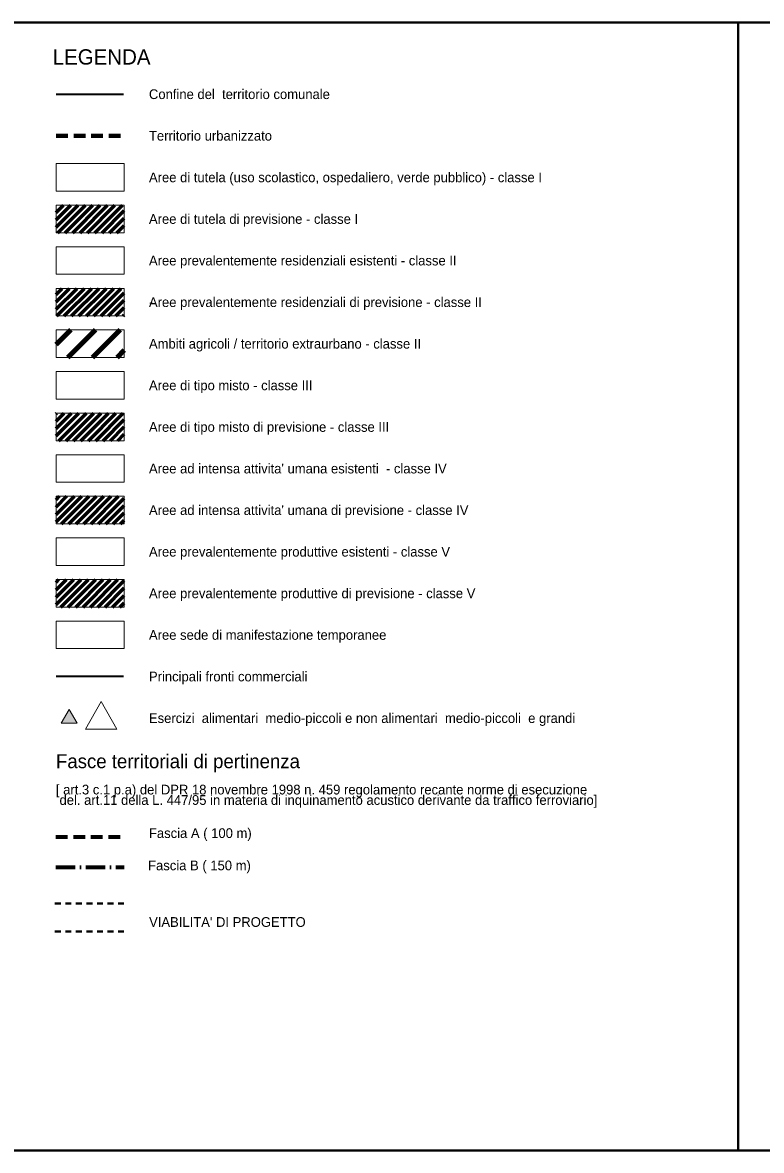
# Model space of a CAD drawing. Extents: x 650468 to 655025, y 889970 to 891591.
# Drawn here: x 651540 to 652602, y 889970 to 891591 of the extents above; entities that cross this region are included whole.
import ezdxf

# ---------------------------------------------------------------- set-up
doc = ezdxf.new("R2010")
doc.units = 0
doc.header["$LTSCALE"] = 5.6
for name, pattern in [('DOT_DASHED', [7.7, 5, -1.2, 0.3, -1.2]), ('MEDIUM_DASHED', [4.5, 3, -1.5]), ('SHORT_DASHED', [2.7, 1.5, -1.2])]:
    doc.linetypes.add(name, pattern=pattern)
doc.layers.add('61', color=7, linetype='Continuous', lineweight=35)

msp = doc.modelspace()

# ---------------------------------------------------------------- hatches: boundary and pattern name
at = {"layer": '61'}
msp.add_hatch(color=256, dxfattribs=at).paths.add_polyline_path([(651606.72, 890603.48), (651618.09, 890583.8), (651595.34, 890583.8)])

# ---------------------------------------------------------------- linework, layer by layer
for p, q in [((651587.95, 891488.17), (651684.93, 891488.17)), ((651684.52, 890650.98), (651587.94, 890650.98))]:
    msp.add_line(p, q, dxfattribs=at)
at = {"layer": '61', "linetype": 'MEDIUM_DASHED', "lineweight": 80}
msp.add_line((651587.94, 891428.36), (651685.6, 891428.36), dxfattribs=at)
at = {"layer": '61', "lineweight": 60}
for p, q in [((651587.94, 891318.24), (651598.26, 891328.56)), ((651587.94, 891307.64), (651608.86, 891328.56)), ((651587.94, 891297.03), (651619.47, 891328.56)), ((651590.48, 891288.96), (651630.08, 891328.56)), ((651601.08, 891288.96), (651640.68, 891328.56)), ((651611.69, 891288.96), (651651.29, 891328.56)), ((651622.3, 891288.96), (651661.9, 891328.56)), ((651632.9, 891288.96), (651672.5, 891328.56)), ((651643.51, 891288.96), (651683.11, 891328.56)), ((651654.12, 891288.96), (651685.86, 891320.7)), ((651664.72, 891288.96), (651685.86, 891310.1)), ((651675.33, 891288.96), (651685.86, 891299.49)), ((651587.94, 891200.22), (651596.7, 891208.98)), ((651587.94, 891189.61), (651607.31, 891208.98)), ((651587.94, 891179.01), (651617.92, 891208.98)), ((651588.92, 891169.38), (651628.52, 891208.98)), ((651599.53, 891169.38), (651639.13, 891208.98)), ((651610.14, 891169.38), (651649.74, 891208.98)), ((651620.74, 891169.38), (651660.34, 891208.98)), ((651631.35, 891169.38), (651670.95, 891208.98)), ((651641.95, 891169.38), (651681.55, 891208.98)), ((651652.56, 891169.38), (651685.86, 891202.68)), ((651663.17, 891169.38), (651685.86, 891192.07)), ((651673.77, 891169.38), (651685.86, 891181.47)), ((651684.38, 891169.38), (651685.86, 891170.86)), ((651587.94, 891028.58), (651588.94, 891029.58)), ((651587.94, 891017.97), (651599.55, 891029.58)), ((651587.94, 891007.36), (651610.16, 891029.58)), ((651587.94, 890996.76), (651620.76, 891029.58)), ((651591.77, 890989.98), (651631.37, 891029.58)), ((651602.38, 890989.98), (651641.98, 891029.58)), ((651612.98, 890989.98), (651652.58, 891029.58)), ((651623.59, 890989.98), (651663.19, 891029.58)), ((651634.2, 890989.98), (651673.8, 891029.58)), ((651644.8, 890989.98), (651684.4, 891029.58)), ((651655.41, 890989.98), (651685.86, 891020.43)), ((651666.02, 890989.98), (651685.86, 891009.82)), ((651676.62, 890989.98), (651685.86, 890999.22)), ((651587.94, 890905.03), (651592.89, 890909.98)), ((651587.94, 890894.43), (651603.49, 890909.98)), ((651587.94, 890883.82), (651614.1, 890909.98)), ((651587.94, 890873.21), (651624.71, 890909.98)), ((651595.71, 890870.38), (651635.31, 890909.98)), ((651606.32, 890870.38), (651645.92, 890909.98)), ((651616.93, 890870.38), (651656.53, 890909.98)), ((651627.53, 890870.38), (651667.13, 890909.98)), ((651638.14, 890870.38), (651677.74, 890909.98)), ((651648.75, 890870.38), (651685.86, 890907.49)), ((651659.35, 890870.38), (651685.86, 890896.89)), ((651669.96, 890870.38), (651685.86, 890886.28)), ((651680.57, 890870.38), (651685.86, 890875.67)), ((651587.94, 890786.34), (651591.98, 890790.38)), ((651587.94, 890775.74), (651602.58, 890790.38)), ((651587.94, 890765.13), (651613.19, 890790.38)), ((651587.94, 890754.52), (651623.8, 890790.38)), ((651594.8, 890750.78), (651634.4, 890790.38)), ((651605.41, 890750.78), (651645.01, 890790.38)), ((651616.02, 890750.78), (651655.62, 890790.38)), ((651626.62, 890750.78), (651666.22, 890790.38)), ((651637.23, 890750.78), (651676.83, 890790.38)), ((651647.84, 890750.78), (651685.86, 890788.8)), ((651658.44, 890750.78), (651685.86, 890778.2)), ((651669.05, 890750.78), (651685.86, 890767.59)), ((651679.66, 890750.78), (651685.86, 890756.98))]:
    msp.add_line(p, q, dxfattribs=at)
at = {"layer": '61', "lineweight": 25}
msp.add_line((651685.59, 891288.96), (651685.86, 891289.33), dxfattribs=at)
at = {"layer": '61', "lineweight": 120}
for p, q in [((651587.94, 891128.06), (651609.09, 891149.21)), ((651604.84, 891109.61), (651644.44, 891149.21)), ((651640.2, 891109.61), (651679.8, 891149.21)), ((651675.55, 891109.61), (651685.86, 891119.92))]:
    msp.add_line(p, q, dxfattribs=at)
at = {"layer": '61', "linetype": 'MEDIUM_DASHED', "lineweight": 70}
msp.add_line((651587.45, 890420.42), (651685.87, 890420.42), dxfattribs=at)
at = {"layer": '61', "linetype": 'DOT_DASHED', "lineweight": 70}
msp.add_line((651587.45, 890376.7), (651685.87, 890376.7), dxfattribs=at)
at = {"layer": '61', "linetype": 'SHORT_DASHED', "lineweight": 40}
for p, q in [((651586.19, 890324.43), (651685.87, 890324.43)), ((651586.19, 890284.43), (651685.87, 890284.43))]:
    msp.add_line(p, q, dxfattribs=at)
at = {"layer": '61', "lineweight": 40}
for points in [[(652568.28, 889969.62), (651518.28, 889969.62), (651518.28, 891591.08)], [(651518.28, 891591.08), (652568.28, 891591.08), (652568.28, 889969.62)]]:
    msp.add_lwpolyline(points, dxfattribs=at)
msp.add_lwpolyline([(653618.27, 891591.08), (653618.27, 889969.62), (652568.28, 889969.62), (652568.28, 891591.08)], close=True, dxfattribs=at)
at = {"layer": '61', "lineweight": 13}
for points in [[(651587.94, 891388.36), (651685.86, 891388.36), (651685.86, 891348.76), (651587.94, 891348.76)], [(651587.94, 891328.56), (651685.86, 891328.56), (651685.86, 891288.96), (651587.94, 891288.96)], [(651587.94, 891268.78), (651685.86, 891268.78), (651685.86, 891229.18), (651587.94, 891229.18)], [(651587.94, 891208.98), (651685.86, 891208.98), (651685.86, 891169.38), (651587.94, 891169.38)], [(651587.94, 891149.21), (651685.86, 891149.21), (651685.86, 891109.61), (651587.94, 891109.61)], [(651587.94, 891089.38), (651685.86, 891089.38), (651685.86, 891049.78), (651587.94, 891049.78)], [(651587.94, 891029.58), (651685.86, 891029.58), (651685.86, 890989.98), (651587.94, 890989.98)], [(651587.94, 890969.78), (651685.86, 890969.78), (651685.86, 890930.18), (651587.94, 890930.18)], [(651587.94, 890909.98), (651685.86, 890909.98), (651685.86, 890870.38), (651587.94, 890870.38)], [(651587.94, 890850.18), (651685.86, 890850.18), (651685.86, 890810.58), (651587.94, 890810.58)], [(651587.94, 890790.38), (651685.86, 890790.38), (651685.86, 890750.78), (651587.94, 890750.78)], [(651587.94, 890730.61), (651685.86, 890730.61), (651685.86, 890691.01), (651587.94, 890691.01)], [(651606.72, 890603.48), (651618.09, 890583.8), (651595.34, 890583.8)], [(651652.65, 890614.79), (651675.39, 890575.41), (651629.92, 890575.41)]]:
    msp.add_lwpolyline(points, close=True, dxfattribs=at)

# ---------------------------------------------------------------- texts
at = {"layer": '61'}
for s, height, p in [('LEGENDA', 22, (651582.99, 891530.68)), ('Confine del  territorio comunale  ', 14, (651721.34, 891481.11)), ('Territorio urbanizzato', 14, (651721.34, 891421.33)), ('Aree di tutela (uso scolastico, ospedaliero, verde pubblico) - classe I', 14, (651721.34, 891361.51)), ('Aree di tutela di previsione - classe I', 14, (651721.34, 891301.71)), ('Aree prevalentemente residenziali esistenti - classe II', 14, (651721.34, 891241.93)), ('Aree prevalentemente residenziali di previsione - classe II', 14, (651721.34, 891182.13)), ('-', 14.06, (651721.34, 891182.1)), ('Ambiti agricoli / territorio extraurbano - classe II', 14, (651721.34, 891122.36)), ('Aree di tipo misto - classe III', 14, (651721.34, 891062.53)), ('Aree di tipo misto di previsione - classe III', 14, (651721.34, 891002.73)), ("Aree ad intensa attivita' umana esistenti  - classe IV", 14, (651721.34, 890942.93)), ("Aree ad intensa attivita' umana di previsione - classe IV", 14, (651721.34, 890883.13)), ('Aree prevalentemente produttive esistenti - classe V', 14, (651721.34, 890823.33)), ('Aree prevalentemente produttive di previsione - classe V', 14, (651721.34, 890763.53)), ('Aree sede di manifestazione temporanee', 14, (651721.34, 890703.76)), ('Principali fronti commerciali', 14, (651721.34, 890643.93)), ('Esercizi  alimentari  medio-piccoli e non alimentari  medio-piccoli  e grandi', 14, (651721.34, 890584.13)), ('Fasce territoriali di pertinenza', 20, (651587.64, 890519.15)), ('[ art.3 c.1 p.a) del DPR 18 novembre 1998 n. 459 regolamento recante norme di esecuzione', 14, (651587.56, 890481.4)), (' del. art.11 della L. 447/95 in materia di inquinamento acustico derivante da traffico ferroviario]', 14, (651587.56, 890466.4)), ('Fascia A ( 100 m)', 14, (651721.34, 890418.79)), ('Fascia B ( 150 m)', 14, (651720.09, 890372.36)), ("VIABILITA' DI PROGETTO", 14, (651721.56, 890291.01))]:
    msp.add_text(s, height=height, dxfattribs=at).set_placement(p)

doc.saveas('drawing.dxf')
